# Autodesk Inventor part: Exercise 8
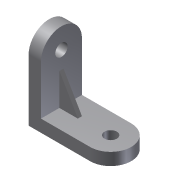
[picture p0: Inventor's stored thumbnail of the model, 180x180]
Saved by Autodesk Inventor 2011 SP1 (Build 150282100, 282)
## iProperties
Created: 2011-02
Part Number: Exercise 8
Document SubType Name: Modeling
Designer: SERGIO
Density: 1 g/cm^3
Author: SERGIO
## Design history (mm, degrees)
sketch "Sketch1"
  geometry: L1 (0, 0)-(-200, 0); L2 (-200, 0)-(-200, 30); L3 (-200, 30)-(-30, 30); L4 (-30, 30)-(-30, 200); L5 (-30, 200)-(0, 200); L6 (0, 200)-(0, 0)
  constraints: 12 end point, 4 parallel, 2 perpendicular, 1 horizontal
  dimensions: "Length" = 200 distance of L1.start L1.end; "d1" = 30 distance of L1.end L2.end; "Height" = 200 distance of L5.end L1.start (= Length)
extrude "Extrusion1" new body sketch "Sketch1" stored distance "d3" = 100; taper "d4" = 0 deg
fillet "Fillet1"
fillet "Fillet2"
sketch "Sketch2"
  geometry: A1 r 50 centre (-120, 50) between (-120, 100) and (-120, 0) reference; 1 further point
hole "Hole1" sketch "Sketch2" at (-120, 50) diameter "Dia_Hole1" = 30; stored, may be unused: countersink angle "d9" = 90 deg, drill point angle "d11" = 118 deg; dims "d6" = 6, "d7" = 4, "d8" = 2, "d10" = 8
sketch "Sketch3"
  geometry: A1 r 50 centre (120, 50) between (120, 0) and (120, 100) reference; 1 further point
hole "Hole2" sketch "Sketch3" at (120, 50) diameter "Dia_Hole2" = 30 (= Dia_Hole1); stored, may be unused: countersink angle "d16" = 90 deg, drill point angle "d18" = 118 deg; dims "d13" = 6, "d14" = 4, "d15" = 2, "d17" = 8
sketch "Sketch4"
  geometry: L1 (-30, 135)-(0, 135) reference; L2 (0, 135)-(0, 0) reference; L3 (0, 0)-(-135, 0) reference; L4 (-135, 0)-(-135, 30) reference; L5 (-135, 30)-(-30, 30) reference; L6 (-30, 30)-(-30, 135) reference; L7 (-30, 200)-(0, 200) reference; L8 (0, 200)-(0, 165) reference; L9 (0, 165)-(-30, 165) reference; L10 (-30, 165)-(-30, 200) reference; L11 (-200, 0)-(-200, 30) reference; L12 (-200, 30)-(-165, 30) reference; L13 (-165, 30)-(-165, 0) reference; L14 (-165, 0)-(-200, 0) reference; L15 (-30, 107.942)-(-75, 30)
  constraints: 2 end point, 2 point on line
  dimensions: "Rib_angle" = 60 deg angle of L5 L15; "d20" = 45 distance of L15.end L5.end
feature "Rib1" sketch "Sketch4" dims "d21" = 1, "d22" = 10, "d23" = 0
body "Solid1"
node "Project Cut Edges1"
